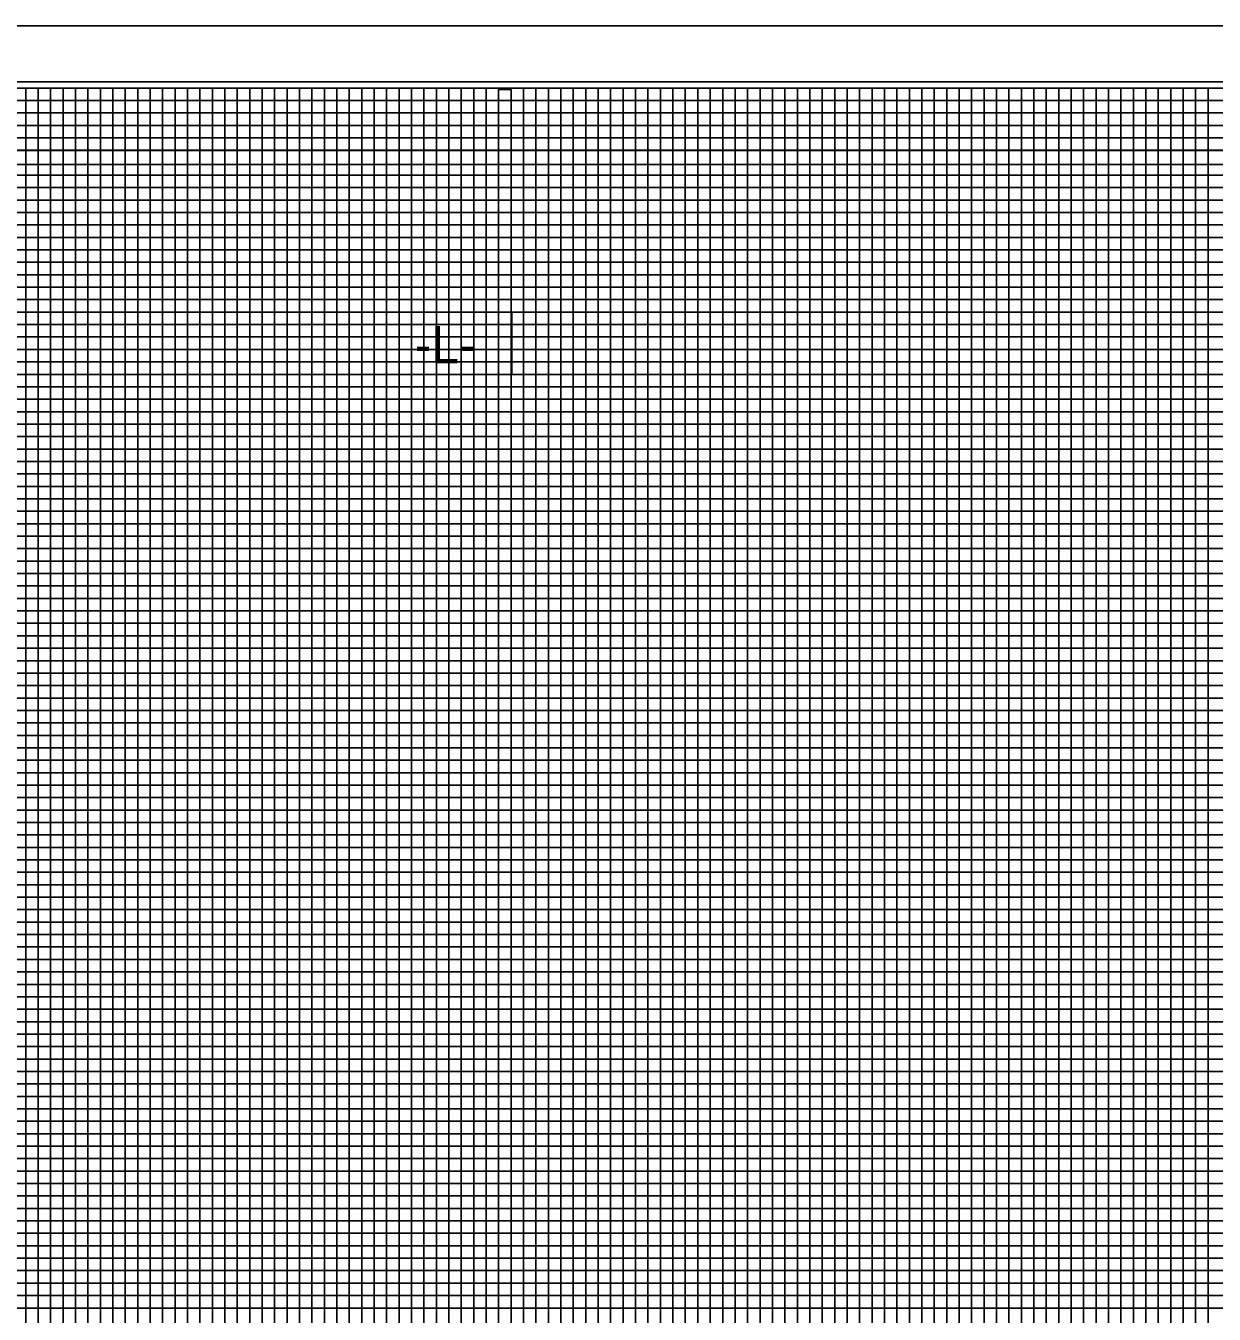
# Model space of a CAD drawing. Extents: x 1728093 to 1729777, y 538013 to 539113.
# Drawn here: x 1728835 to 1729312, y 538595 to 539113 of the extents above; entities that cross this region are included whole.
import ezdxf

# ---------------------------------------------------------------- set-up
doc = ezdxf.new("R2010")
doc.units = 0
for name, color, linetype in [('Prop Grid Mask', 7, 'Continuous'), ('Prop VPI Label', 7, 'Continuous'), ('Scratch_Level_0', 7, 'Continuous'), ('Sheet Cutting Line CELL', 7, 'Continuous'), ('Sheet DOT Grid CELL', 7, 'Continuous'), ('Sheet Plot Border Inside CELL', 7, 'Continuous'), ('Sheet Plot Border Outside CELL', 7, 'Continuous'), ('Sheet Profile CELL', 7, 'Continuous'), ('Sheet Profile Grid Major CELL', 7, 'Continuous'), ('Sheet Profile Grid Middle CELL', 7, 'Continuous'), ('Sheet Profile Grid Minor CELL', 7, 'Continuous')]:
    doc.layers.add(name, color=color, linetype=linetype)

msp = doc.modelspace()

# ---------------------------------------------------------------- linework, layer by layer
at = {"layer": 'Prop Grid Mask'}
msp.add_lwpolyline([(1728989.89, 538997.97), (1729030.16, 538997.97), (1729030.16, 538972.97), (1728989.89, 538972.97)], close=True, dxfattribs=at)
at = {"layer": 'Scratch_Level_0'}
msp.add_lwpolyline([(1728309.89, 539087.97), (1729709.89, 539087.97), (1729709.89, 538062.97), (1728309.89, 538062.97)], close=True, dxfattribs=at)
at = {"layer": 'Sheet Cutting Line CELL'}
msp.add_line((1729776.89, 539112.97), (1728092.89, 539112.97), dxfattribs=at)
at = {"layer": 'Sheet DOT Grid CELL'}
for p, q in [((1728859.89, 539087.97), (1728859.89, 538062.97)), ((1728909.89, 539087.97), (1728909.89, 538062.97)), ((1728959.89, 539087.97), (1728959.89, 538062.97)), ((1729009.89, 539087.97), (1729009.89, 538062.97)), ((1729059.89, 539087.97), (1729059.89, 538062.97)), ((1729109.89, 539087.97), (1729109.89, 538062.97)), ((1729159.89, 539087.97), (1729159.89, 538062.97)), ((1729209.89, 539087.97), (1729209.89, 538062.97)), ((1729259.89, 539087.97), (1729259.89, 538062.97)), ((1729309.89, 539087.97), (1729309.89, 538062.97)), ((1728259.89, 539062.97), (1729559.84, 539062.97)), ((1728259.89, 539012.97), (1729559.84, 539012.97)), ((1728259.89, 538962.97), (1729559.84, 538962.97)), ((1728259.89, 538912.97), (1729759.89, 538912.97)), ((1728259.89, 538862.97), (1729759.89, 538862.97)), ((1728259.89, 538812.97), (1729759.89, 538812.97)), ((1728259.89, 538762.97), (1729759.89, 538762.97)), ((1728259.89, 538712.97), (1729759.89, 538712.97)), ((1728259.89, 538612.97), (1729759.89, 538612.97))]:
    msp.add_line(p, q, dxfattribs=at)
at = {"layer": 'Sheet Plot Border Inside CELL'}
msp.add_lwpolyline([(1729772.39, 539090.52), (1728105.89, 539090.52), (1728105.89, 538035.42), (1729772.39, 538035.42)], close=True, dxfattribs=at)
at = {"layer": 'Sheet Plot Border Outside CELL'}
msp.add_lwpolyline([(1729776.89, 539112.97), (1728092.89, 539112.97), (1728092.89, 538012.97), (1729776.89, 538012.97)], close=True, dxfattribs=at)
at = {"layer": 'Sheet Profile CELL'}
msp.add_lwpolyline([(1729759.89, 539087.97), (1728259.89, 539087.97), (1728259.89, 538037.97), (1729759.89, 538037.97)], close=True, dxfattribs=at)
at = {"layer": 'Sheet Profile Grid Major CELL'}
for points in [[(1728859.89, 538062.97), (1728859.89, 539087.97), (1728909.89, 539087.97), (1728909.89, 538062.97)], [(1728959.89, 538062.97), (1728959.89, 539087.97), (1729009.89, 539087.97), (1729009.89, 538062.97)], [(1729059.89, 538062.97), (1729059.89, 539087.97), (1729109.89, 539087.97), (1729109.89, 538062.97)], [(1729159.89, 538062.97), (1729159.89, 539087.97), (1729209.89, 539087.97), (1729209.89, 538062.97)], [(1729259.89, 538062.97), (1729259.89, 539087.97), (1729309.89, 539087.97), (1729309.89, 538062.97)], [(1729559.84, 539012.97), (1728259.99, 539012.97), (1728259.99, 539062.92), (1729559.84, 539062.92)], [(1729759.89, 538912.97), (1728259.89, 538912.97), (1728259.89, 538962.97), (1729559.84, 538962.97)], [(1729759.89, 538812.97), (1728259.89, 538812.97), (1728259.89, 538862.97), (1729759.89, 538862.97)], [(1729759.89, 538712.97), (1728259.89, 538712.97), (1728259.89, 538762.97), (1729759.89, 538762.97)], [(1729759.89, 538612.97), (1728259.89, 538612.97), (1728259.89, 538662.97), (1729759.89, 538662.97)]]:
    msp.add_lwpolyline(points, dxfattribs=at)
at = {"layer": 'Sheet Profile Grid Middle CELL'}
for points in [[(1728834.89, 538062.97), (1728834.89, 539087.97), (1728884.89, 539087.97), (1728884.89, 538062.97)], [(1728934.89, 538062.97), (1728934.89, 539087.97), (1728984.89, 539087.97), (1728984.89, 538062.97)], [(1729034.89, 538062.97), (1729034.89, 539087.97), (1729084.89, 539087.97), (1729084.89, 538062.97)], [(1729134.89, 538062.97), (1729134.89, 539087.97), (1729184.89, 539087.97), (1729184.89, 538062.97)], [(1729234.89, 538062.97), (1729234.89, 539087.97), (1729284.89, 539087.97), (1729284.89, 538062.97)], [(1728259.89, 539037.97), (1729559.84, 539037.97)], [(1729559.84, 538987.97), (1728259.89, 538987.97), (1728259.89, 538937.92), (1729559.84, 538937.92)], [(1729599.88, 538887.97), (1728259.89, 538887.97), (1728259.89, 538837.97), (1729759.89, 538837.97)], [(1729759.89, 538787.97), (1728259.89, 538787.97), (1728259.89, 538737.97), (1729759.89, 538737.97)], [(1729759.89, 538687.97), (1728259.89, 538687.97), (1728259.89, 538637.97), (1729759.89, 538637.97)]]:
    msp.add_lwpolyline(points, dxfattribs=at)
at = {"layer": 'Sheet Profile Grid Minor CELL'}
for p, q in [((1729709.89, 538922.97), (1728309.89, 538922.97)), ((1728309.89, 538917.97), (1729709.89, 538917.97)), ((1729709.89, 538907.97), (1728309.89, 538907.97)), ((1728309.89, 538902.97), (1729599.88, 538902.97)), ((1729599.88, 538882.97), (1728309.89, 538882.97)), ((1729709.89, 538852.97), (1728309.89, 538852.97)), ((1728309.89, 538847.97), (1729709.89, 538847.97))]:
    msp.add_line(p, q, dxfattribs=at)
for points in [[(1728839.89, 538062.97), (1728839.89, 539087.97), (1728844.89, 539087.97), (1728844.89, 538062.97)], [(1728849.89, 538062.97), (1728849.89, 539087.97), (1728854.89, 539087.97), (1728854.89, 538062.97)], [(1728864.89, 538062.97), (1728864.89, 539087.97), (1728869.89, 539087.97), (1728869.89, 538062.97)], [(1728874.89, 538062.97), (1728874.89, 539087.97), (1728879.89, 539087.97), (1728879.89, 538062.97)], [(1728889.89, 538062.97), (1728889.89, 539087.97), (1728894.89, 539087.97), (1728894.89, 538062.97)], [(1728899.89, 538062.97), (1728899.89, 539087.97), (1728904.89, 539087.97), (1728904.89, 538062.97)], [(1728914.89, 538062.97), (1728914.89, 539087.97), (1728919.89, 539087.97), (1728919.89, 538062.97)], [(1728924.89, 538062.97), (1728924.89, 539087.97), (1728929.89, 539087.97), (1728929.89, 538062.97)], [(1728939.89, 538062.97), (1728939.89, 539087.97), (1728944.89, 539087.97), (1728944.89, 538062.97)], [(1728949.89, 538062.97), (1728949.89, 539087.97), (1728954.89, 539087.97), (1728954.89, 538062.97)], [(1728964.89, 538062.97), (1728964.89, 539087.97), (1728969.89, 539087.97), (1728969.89, 538062.97)], [(1728974.89, 538062.97), (1728974.89, 539087.97), (1728979.89, 539087.97), (1728979.89, 538062.97)], [(1728989.89, 538062.97), (1728989.89, 539087.97), (1728994.89, 539087.97), (1728994.89, 538062.97)], [(1728999.89, 538062.97), (1728999.89, 539087.97), (1729004.89, 539087.97), (1729004.89, 538062.97)], [(1729014.89, 538062.97), (1729014.89, 539087.97), (1729019.89, 539087.97), (1729019.89, 538062.97)], [(1729024.89, 538062.97), (1729024.89, 539087.37), (1729029.89, 539087.37), (1729029.89, 538062.97)], [(1729039.89, 538062.97), (1729039.89, 539087.97), (1729044.89, 539087.97), (1729044.89, 538062.97)], [(1729049.89, 538062.97), (1729049.89, 539087.97), (1729054.89, 539087.97), (1729054.89, 538062.97)], [(1729064.89, 538062.97), (1729064.89, 539087.97), (1729069.89, 539087.97), (1729069.89, 538062.97)], [(1729074.89, 538062.97), (1729074.89, 539087.97), (1729079.89, 539087.97), (1729079.89, 538062.97)], [(1729089.89, 538062.97), (1729089.89, 539087.97), (1729094.89, 539087.97), (1729094.89, 538062.97)], [(1729099.89, 538062.97), (1729099.89, 539087.97), (1729104.89, 539087.97), (1729104.89, 538062.97)], [(1729114.89, 538062.97), (1729114.89, 539087.97), (1729119.89, 539087.97), (1729119.89, 538062.97)], [(1729124.89, 538062.97), (1729124.89, 539087.97), (1729129.89, 539087.97), (1729129.89, 538062.97)], [(1729139.89, 538062.97), (1729139.89, 539087.97), (1729144.89, 539087.97), (1729144.89, 538062.97)], [(1729149.89, 538062.97), (1729149.89, 539087.97), (1729154.89, 539087.97), (1729154.89, 538062.97)], [(1729164.89, 538062.97), (1729164.89, 539087.97), (1729169.89, 539087.97), (1729169.89, 538062.97)], [(1729174.89, 538062.97), (1729174.89, 539087.97), (1729179.89, 539087.97), (1729179.89, 538062.97)], [(1729189.89, 538062.97), (1729189.89, 539087.97), (1729194.89, 539087.97), (1729194.89, 538062.97)], [(1729199.89, 538062.97), (1729199.89, 539087.97), (1729204.89, 539087.97), (1729204.89, 538062.97)], [(1729214.89, 538062.97), (1729214.89, 539087.97), (1729219.89, 539087.97), (1729219.89, 538062.97)], [(1729224.89, 538062.97), (1729224.89, 539087.97), (1729229.89, 539087.97), (1729229.89, 538062.97)], [(1729239.89, 538062.97), (1729239.89, 539087.97), (1729244.89, 539087.97), (1729244.89, 538062.97)], [(1729249.89, 538062.97), (1729249.89, 539087.97), (1729254.89, 539087.97), (1729254.89, 538062.97)], [(1729264.89, 538062.97), (1729264.89, 539087.97), (1729269.89, 539087.97), (1729269.89, 538062.97)], [(1729274.89, 538062.97), (1729274.89, 539087.97), (1729279.89, 539087.97), (1729279.89, 538062.97)], [(1729289.89, 538062.97), (1729289.89, 539087.97), (1729294.89, 539087.97), (1729294.89, 538062.97)], [(1729299.89, 538062.97), (1729299.89, 539087.97), (1729304.89, 539087.97), (1729304.89, 538062.97)], [(1729559.84, 539082.97), (1728309.89, 539082.97), (1728309.89, 539077.97), (1729559.84, 539077.97)], [(1729559.84, 539072.97), (1728309.89, 539072.97), (1728309.89, 539067.97), (1729559.84, 539067.97)], [(1729559.84, 539057.22), (1728310.89, 539057.22), (1728310.89, 539052.97), (1729559.84, 539052.97)], [(1729559.84, 539047.97), (1728309.89, 539047.97), (1728309.89, 539042.97), (1729559.84, 539042.97)], [(1729559.84, 539032.97), (1728309.89, 539032.97), (1728309.89, 539027.97), (1729559.84, 539027.97)], [(1729559.84, 539022.97), (1728309.89, 539022.97), (1728309.89, 539017.97), (1729559.84, 539017.97)], [(1729559.84, 539007.97), (1728309.89, 539007.97), (1728309.89, 539002.97), (1729559.84, 539002.97)], [(1729559.84, 538997.97), (1728309.89, 538997.97), (1728309.89, 538992.97), (1729559.84, 538992.97)], [(1729559.84, 538982.97), (1728309.89, 538982.97), (1728309.89, 538977.97), (1729559.84, 538977.97)], [(1729559.84, 538972.97), (1728309.89, 538972.97), (1728309.89, 538967.97), (1729559.84, 538967.97)], [(1729559.84, 538957.97), (1728309.89, 538957.97), (1728309.89, 538952.97), (1729559.84, 538952.97)], [(1729559.84, 538947.97), (1728309.89, 538947.97), (1728309.89, 538947.97), (1728309.89, 538927.97), (1729559.84, 538927.97)], [(1728309.89, 538942.97), (1729559.84, 538942.97)], [(1729559.84, 538932.97), (1728309.89, 538932.97)], [(1729599.88, 538897.97), (1728309.89, 538897.97), (1728309.89, 538892.97), (1729599.88, 538892.97)], [(1729599.88, 538877.97), (1728309.89, 538877.97), (1728309.89, 538872.97), (1729599.88, 538872.97)], [(1729709.89, 538867.97), (1728309.89, 538867.97)], [(1728309.89, 538857.97), (1729709.89, 538857.97)], [(1729709.89, 538842.97), (1728309.89, 538842.97), (1728309.89, 538832.97), (1729709.89, 538832.97)], [(1729709.89, 538827.97), (1728309.89, 538827.97), (1728309.89, 538822.97), (1729709.89, 538822.97)], [(1729709.89, 538817.97), (1728309.89, 538817.97), (1728309.89, 538807.97), (1729709.89, 538807.97)], [(1729709.89, 538802.97), (1728309.89, 538802.97), (1728309.89, 538797.97), (1729709.89, 538797.97)], [(1729709.89, 538792.97), (1728309.89, 538792.97), (1728309.89, 538782.97), (1729709.89, 538782.97)], [(1729709.89, 538777.97), (1728309.89, 538777.97), (1728309.89, 538772.97), (1729709.89, 538772.97)], [(1729709.89, 538767.97), (1728309.89, 538767.97), (1728309.89, 538757.97), (1729709.89, 538757.97)], [(1729709.89, 538752.97), (1728309.89, 538752.97), (1728309.89, 538747.97), (1729709.89, 538747.97)], [(1729709.89, 538742.97), (1728309.89, 538742.97), (1728309.89, 538732.97), (1729709.89, 538732.97)], [(1729709.89, 538727.97), (1728309.89, 538727.97), (1728309.89, 538722.97), (1729709.89, 538722.97)], [(1729709.89, 538717.97), (1728309.89, 538717.97), (1728309.89, 538707.97), (1729709.89, 538707.97)], [(1729709.89, 538702.97), (1728309.89, 538702.97), (1728309.89, 538697.97), (1729709.89, 538697.97)], [(1729709.89, 538692.97), (1728309.89, 538692.97), (1728309.89, 538682.97), (1729709.89, 538682.97)], [(1729709.89, 538677.97), (1728309.89, 538677.97), (1728309.89, 538672.97), (1729709.89, 538672.97)], [(1729709.89, 538667.97), (1728309.89, 538667.97), (1728309.89, 538657.97), (1729709.89, 538657.97)], [(1729709.89, 538652.97), (1728309.89, 538652.97), (1728309.89, 538647.97), (1729709.89, 538647.97)], [(1729709.89, 538642.97), (1728309.89, 538642.97), (1728309.89, 538632.97), (1729709.89, 538632.97)], [(1729709.89, 538627.97), (1728309.89, 538627.97), (1728309.89, 538622.97), (1729709.89, 538622.97)], [(1729709.89, 538617.97), (1728309.89, 538617.97), (1728309.89, 538607.97), (1729709.89, 538607.97)], [(1729709.89, 538602.97), (1728309.89, 538602.97), (1728309.89, 538597.97), (1729709.89, 538597.97)]]:
    msp.add_lwpolyline(points, dxfattribs=at)

# ---------------------------------------------------------------- texts
at = {"layer": 'Prop VPI Label'}
msp.add_text('-L-', height=15, rotation=360, dxfattribs=at).set_placement((1728991.13, 538977.43))

doc.saveas('drawing.dxf')
